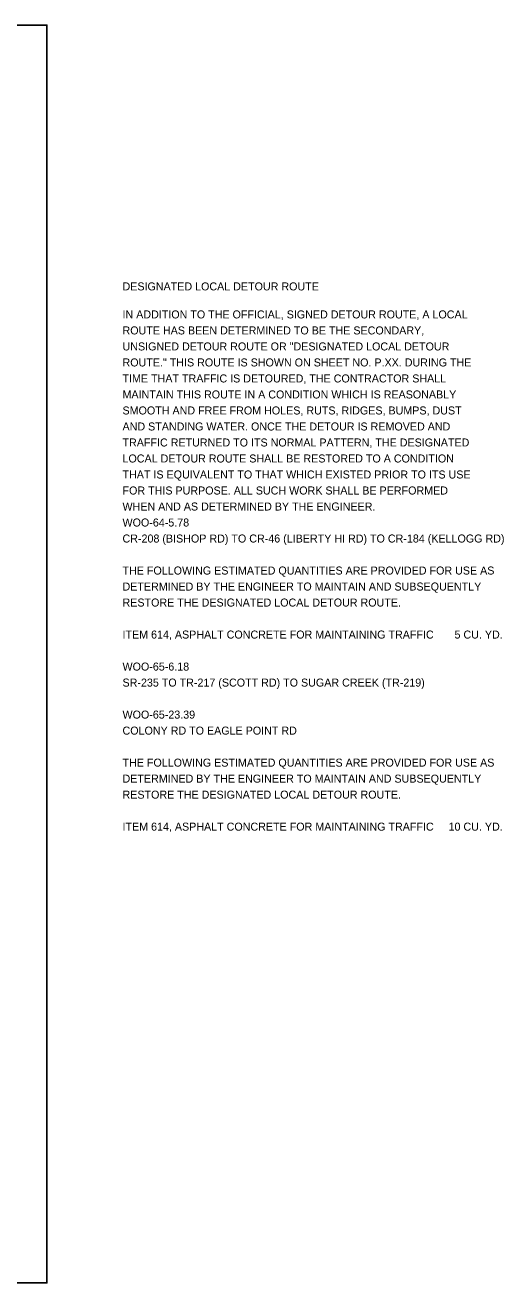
# Model space of a CAD drawing. Extents: x 0 to 42, y 0 to 22.
# Drawn here: x 33.62 to 41.99, y 0 to 22 of the extents above; entities that cross this region are included whole.
import ezdxf

# ---------------------------------------------------------------- set-up
doc = ezdxf.new("R2010")
doc.units = 0
doc.layers.add('SH_Cut_Line', color=7, linetype='Continuous')
doc.layers.add('SH_Text', color=7, linetype='Continuous')

msp = doc.modelspace()

# ---------------------------------------------------------------- linework, layer by layer
at = {"layer": 'SH_Cut_Line'}
msp.add_lwpolyline([(0, 0), (34, 0), (34, 22), (0, 22)], close=True, dxfattribs=at)

# ---------------------------------------------------------------- texts
at = {"layer": 'SH_Text'}
for s, p in [('DESIGNATED LOCAL DETOUR ROUTE', (35.321, 17.36)), ('IN ADDITION TO THE OFFICIAL, SIGNED DETOUR ROUTE, A LOCAL', (35.321, 16.87)), ('ROUTE HAS BEEN DETERMINED TO BE THE SECONDARY,', (35.321, 16.59)), ('UNSIGNED DETOUR ROUTE OR "DESIGNATED LOCAL DETOUR', (35.321, 16.31)), ('ROUTE." THIS ROUTE IS SHOWN ON SHEET NO. P.XX. DURING THE', (35.321, 16.03)), ('TIME THAT TRAFFIC IS DETOURED, THE CONTRACTOR SHALL', (35.321, 15.75)), ('MAINTAIN THIS ROUTE IN A CONDITION WHICH IS REASONABLY', (35.321, 15.47)), ('SMOOTH AND FREE FROM HOLES, RUTS, RIDGES, BUMPS, DUST', (35.321, 15.19)), ('AND STANDING WATER. ONCE THE DETOUR IS REMOVED AND', (35.321, 14.91)), ('TRAFFIC RETURNED TO ITS NORMAL PATTERN, THE DESIGNATED', (35.321, 14.63)), ('LOCAL DETOUR ROUTE SHALL BE RESTORED TO A CONDITION', (35.321, 14.35)), ('THAT IS EQUIVALENT TO THAT WHICH EXISTED PRIOR TO ITS USE', (35.321, 14.07)), ('FOR THIS PURPOSE. ALL SUCH WORK SHALL BE PERFORMED', (35.321, 13.79)), ('WHEN AND AS DETERMINED BY THE ENGINEER.', (35.321, 13.51)), ('WOO-64-5.78', (35.321, 13.23)), ('CR-208 (BISHOP RD) TO CR-46 (LIBERTY HI RD) TO CR-184 (KELLOGG RD)', (35.321, 12.95)), ('THE FOLLOWING ESTIMATED QUANTITIES ARE PROVIDED FOR USE AS ', (35.321, 12.39)), ('DETERMINED BY THE ENGINEER TO MAINTAIN AND SUBSEQUENTLY ', (35.321, 12.11)), ('RESTORE THE DESIGNATED LOCAL DETOUR ROUTE.', (35.321, 11.83)), ('ITEM 614, ASPHALT CONCRETE FOR MAINTAINING TRAFFIC       5 CU. YD.', (35.321, 11.27)), ('WOO-65-6.18', (35.321, 10.71)), ('SR-235 TO TR-217 (SCOTT RD) TO SUGAR CREEK (TR-219)', (35.321, 10.43)), ('WOO-65-23.39', (35.321, 9.87)), ('COLONY RD TO EAGLE POINT RD', (35.321, 9.59)), ('THE FOLLOWING ESTIMATED QUANTITIES ARE PROVIDED FOR USE AS ', (35.321, 9.03)), ('DETERMINED BY THE ENGINEER TO MAINTAIN AND SUBSEQUENTLY ', (35.321, 8.75)), ('RESTORE THE DESIGNATED LOCAL DETOUR ROUTE.', (35.321, 8.47)), ('ITEM 614, ASPHALT CONCRETE FOR MAINTAINING TRAFFIC     10 CU. YD.', (35.321, 7.91))]:
    msp.add_text(s, height=0.14, dxfattribs=at).set_placement(p)

doc.saveas('drawing.dxf')
